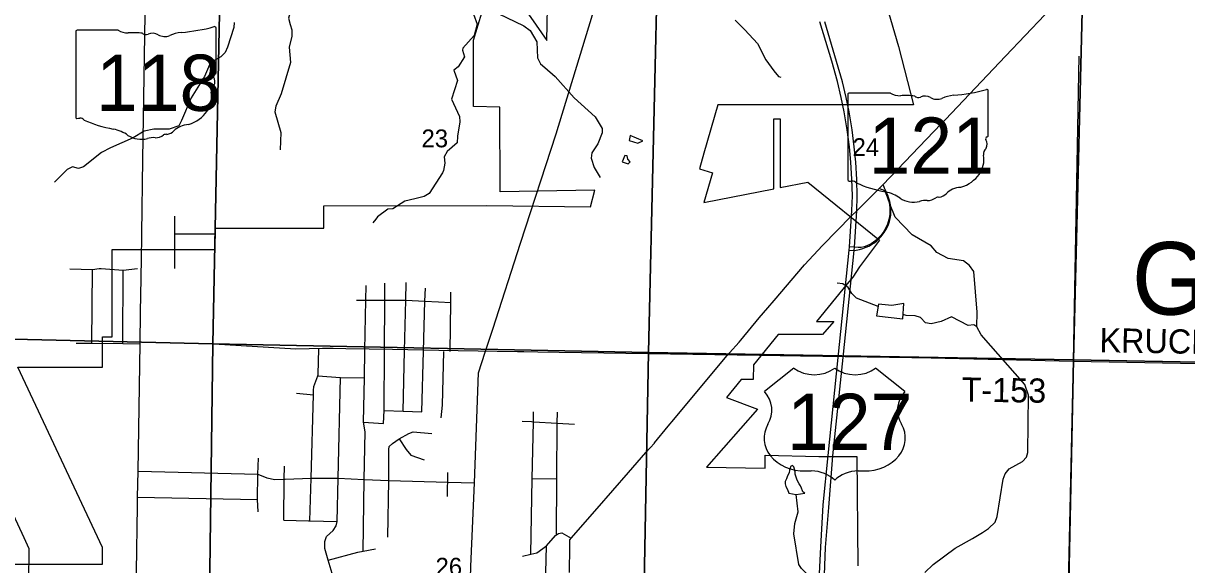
# Model space of a CAD drawing. Extents: x 0 to 68.9, y -26.1 to 22.
# Drawn here: x 4.831 to 7.562, y 18.387 to 19.658 of the extents above; entities that cross this region are included whole.
import ezdxf

# ---------------------------------------------------------------- set-up
doc = ezdxf.new("R2010")
doc.units = 0
for name, color, linetype in [('GM_X_City_Street', 7, 'Continuous'), ('GM_X_Corporation', 7, 'Continuous'), ('GM_X_County_Road', 7, 'Continuous'), ('GM_X_Interchange_Ramps', 7, 'Continuous'), ('GM_X_Minor_Lake', 7, 'Continuous'), ('GM_X_Minor_River', 7, 'Continuous'), ('GM_X_Section_Text', 7, 'Continuous'), ('GM_X_State_Location', 7, 'Continuous'), ('GM_X_State_Route', 7, 'Continuous'), ('GM_X_State_Shield', 7, 'Continuous'), ('GM_X_Township_Road', 7, 'Continuous'), ('GM_X_Township_Road_Text', 7, 'Continuous'), ('GM_X_Township_Text', 7, 'Continuous'), ('GM_X_US_Location', 7, 'Continuous'), ('GM_X_US_Route', 7, 'Continuous'), ('GM_X_US_Shield', 7, 'Continuous')]:
    doc.layers.add(name, color=color, linetype=linetype)

msp = doc.modelspace()

# ---------------------------------------------------------------- linework, layer by layer
at = {"layer": 'GM_X_City_Street'}
for p, q in [((4.9917, 18.9071), (4.9933, 19.0806)), ((5.0641, 18.9065), (5.0649, 19.0787)), ((5.4719, 18.7899), (5.5117, 18.7861)), ((5.1002, 18.6064), (5.3814, 18.6)), ((6.0255, 18.5889), (6.0831, 18.5892)), ((5.0992, 18.546), (5.3803, 18.54))]:
    msp.add_line(p, q, dxfattribs=at)
for points in [[(4.9398, 19.0822), (4.9933, 19.0806), (5.0092, 19.0824), (5.0132, 19.0828), (5.0649, 19.0787), (5.0985, 19.0827)], [(5.6292, 18.722), (5.6313, 18.8257), (5.6327, 18.8912), (5.6351, 19.0083), (5.6358, 19.0426)], [(5.6292, 18.722), (5.6763, 18.7184), (5.6775, 18.749), (5.7223, 18.748), (5.7658, 18.7464), (5.7701, 18.8888), (5.7736, 19.0059), (5.7745, 19.0364)], [(5.6775, 18.749), (5.6783, 18.8904), (5.679, 19.0083), (5.6792, 19.0485)], [(5.7223, 18.748), (5.7258, 18.8896), (5.7287, 19.0082), (5.7297, 19.0496)], [(5.6127, 19.0083), (5.6351, 19.0083), (5.679, 19.0083), (5.7287, 19.0082), (5.7736, 19.0059), (5.8054, 19.0043), (5.8342, 19.0028)], [(5.8328, 18.8878), (5.8342, 19.0028), (5.8345, 19.0271)], [(4.9551, 18.9074), (4.9917, 18.9071), (5.0641, 18.9065), (5.1048, 18.9061)], [(5.5036, 18.4901), (5.5064, 18.5901), (5.5117, 18.7861), (5.512, 18.7963), (5.5127, 18.8058), (5.5221, 18.8309), (5.523, 18.8332), (5.523, 18.8342), (5.5245, 18.893)], [(5.8116, 18.7317), (5.8149, 18.7616), (5.8179, 18.888)], [(5.5221, 18.8309), (5.5755, 18.8267), (5.6313, 18.8257)], [(5.6231, 18.3657), (5.6105, 18.3638), (5.5966, 18.3559), (5.5851, 18.3505), (5.5752, 18.3516), (5.5644, 18.3573), (5.556, 18.3663), (5.5465, 18.398), (5.5384, 18.425), (5.5382, 18.4417), (5.5423, 18.4537), (5.558, 18.4677), (5.5655, 18.4782), (5.5677, 18.4883), (5.5701, 18.59), (5.5755, 18.8267)], [(6.0224, 18.4116), (6.0255, 18.5889), (6.0279, 18.7228), (6.0283, 18.7457)], [(6.0821, 18.4572), (6.0831, 18.5892), (6.0841, 18.7194), (6.0843, 18.7449)], [(5.6283, 18.4188), (5.6312, 18.5874), (5.6331, 18.6991), (5.6292, 18.722)], [(6.0015, 18.7243), (6.0239, 18.723), (6.0279, 18.7228), (6.0841, 18.7194), (6.1248, 18.717)], [(5.6865, 18.4519), (5.6884, 18.5849), (5.6887, 18.6575), (5.6897, 18.6647), (5.6971, 18.6717), (5.713, 18.683), (5.7357, 18.6951), (5.746, 18.699), (5.7898, 18.6954)], [(5.713, 18.683), (5.7291, 18.6576), (5.7402, 18.6444), (5.7719, 18.6331)], [(5.3817, 18.5115), (5.3803, 18.54), (5.3814, 18.6), (5.3826, 18.6369)], [(5.3814, 18.6), (5.4024, 18.591), (5.4209, 18.5874), (5.4432, 18.5881), (5.4456, 18.5882), (5.5064, 18.5901), (5.5093, 18.5901), (5.5701, 18.59), (5.6312, 18.5874), (5.6884, 18.5849), (5.8269, 18.5812), (5.8901, 18.5795)], [(5.4422, 18.4918), (5.4432, 18.5881), (5.4435, 18.6187)], [(5.8263, 18.5475), (5.8267, 18.5698), (5.8269, 18.5812), (5.8272, 18.6033)], [(5.4422, 18.4918), (5.5001, 18.4902), (5.5036, 18.4901), (5.5677, 18.4883)], [(6.0028, 18.4075), (6.0224, 18.4116), (6.0365, 18.4147), (6.059, 18.4313), (6.0802, 18.4559), (6.0821, 18.4572), (6.0871, 18.4606), (6.0948, 18.4616), (6.1165, 18.4491)], [(5.5465, 18.398), (5.6158, 18.4163), (5.6283, 18.4188), (5.6572, 18.4247)], [(6.0526, 18.202), (6.0572, 18.3679), (6.059, 18.4313)]]:
    msp.add_lwpolyline(points, dxfattribs=at)
at = {"layer": 'GM_X_Corporation'}
for points in [[(4.2937, 19.9358), (5.2957, 19.9154), (5.2753, 18.9061), (4.2714, 18.9289)], [(6.3218, 19.8939), (6.2983, 18.8857), (5.2753, 18.9061), (5.2957, 19.9154)], [(6.3218, 19.8939), (7.3211, 19.8752), (7.2954, 18.8682), (6.2983, 18.8857)], [(8.3254, 19.8572), (8.2978, 18.8494), (7.2954, 18.8682), (7.3211, 19.8752)], [(4.2714, 18.9289), (5.2753, 18.9061), (5.2626, 17.9001), (4.25, 17.9235)], [(5.2753, 18.9061), (6.2983, 18.8857), (6.2791, 17.8826), (5.2626, 17.9001)], [(6.2983, 18.8857), (7.2954, 18.8682), (7.2743, 17.8636), (6.2791, 17.8826)], [(7.2954, 18.8682), (8.2978, 18.8494), (8.2824, 17.8496), (7.2743, 17.8636)]]:
    msp.add_lwpolyline(points, close=True, dxfattribs=at)
for points in [[(5.9913, 19.7169), (6.0597, 19.6181), (6.0645, 19.8504)], [(6.8284, 19.7974), (6.885, 19.6036), (6.9201, 19.4673), (6.4613, 19.4672), (6.428, 19.3531), (6.4176, 19.3167), (6.4481, 19.3074), (6.4281, 19.2378), (6.5923, 19.2698), (6.5923, 19.4338), (6.6075, 19.4341), (6.6075, 19.2727), (6.6719, 19.2852), (6.8402, 19.1491), (6.7933, 19.0868), (6.778, 19.0624), (6.7644, 19.0467), (6.6928, 18.9583), (6.7334, 18.9581), (6.707, 18.9279), (6.6028, 18.9279), (6.5449, 18.8563), (6.5437, 18.822), (6.5161, 18.8216), (6.481, 18.7797), (6.5537, 18.7523), (6.4346, 18.616), (6.5723, 18.6136), (6.5723, 18.6228), (6.5723, 18.644), (6.698, 18.6411), (6.7872, 18.6414), (6.7897, 18.3841)], [(4.7703, 18.3886), (5.0167, 18.3887), (5.0167, 18.4272), (4.8182, 18.8508), (5.0165, 18.8509), (5.0165, 18.9225), (5.0392, 18.9225), (5.0392, 19.1269), (5.2809, 19.127), (5.2817, 19.177), (5.5365, 19.1771), (5.5365, 19.2301), (5.9191, 19.2302), (6.1624, 19.2277), (6.172, 19.2662), (5.9497, 19.2623), (5.9496, 19.4617), (5.8873, 19.4628), (5.8873, 19.6186), (5.9181, 19.7194)]]:
    msp.add_lwpolyline(points, dxfattribs=at)
at = {"layer": 'GM_X_County_Road'}
msp.add_line((5.9326, 18.9401), (5.9979, 19.1418), dxfattribs=at)
for points in [[(5.9979, 19.1418), (6.0812, 19.3992), (6.2297, 19.8842)], [(5.876, 18.0868), (5.8738, 18.1354), (5.8764, 18.2174), (5.8815, 18.3829), (5.8901, 18.5795), (5.899, 18.8376), (5.9152, 18.8864), (5.9326, 18.9401)]]:
    msp.add_lwpolyline(points, dxfattribs=at)
at = {"layer": 'GM_X_Interchange_Ramps'}
for points in [[(6.7694, 19.1253), (6.7809, 19.1248), (6.7854, 19.1253), (6.7932, 19.1275), (6.8012, 19.1298), (6.8094, 19.1328), (6.8152, 19.1354), (6.8219, 19.1389), (6.8285, 19.1432), (6.8345, 19.1476), (6.8441, 19.1574), (6.8516, 19.1673), (6.8577, 19.1775), (6.8613, 19.1856), (6.8637, 19.1933), (6.8655, 19.2004), (6.8667, 19.2077), (6.8672, 19.2156), (6.8671, 19.2241), (6.8663, 19.2319), (6.8646, 19.2402), (6.8626, 19.247), (6.86, 19.2545), (6.8561, 19.2629), (6.8541, 19.2667), (6.8519, 19.2716), (6.8505, 19.276), (6.8497, 19.2777), (6.8483, 19.279)], [(6.8406, 19.2715), (6.842, 19.27), (6.8445, 19.2689), (6.8466, 19.2685), (6.8488, 19.2677), (6.8508, 19.2665), (6.8526, 19.2648), (6.8552, 19.2588), (6.8582, 19.2512), (6.8603, 19.2463), (6.8628, 19.2377), (6.864, 19.2316), (6.8647, 19.2252), (6.8648, 19.2184), (6.8645, 19.2113), (6.864, 19.205), (6.8626, 19.1976), (6.8592, 19.1864), (6.8546, 19.1762), (6.8489, 19.167), (6.8434, 19.16), (6.8372, 19.1535), (6.8295, 19.1469), (6.8205, 19.1407), (6.811, 19.1359), (6.8041, 19.1336), (6.797, 19.1317), (6.7903, 19.1319), (6.7817, 19.133), (6.7702, 19.1336)]]:
    msp.add_lwpolyline(points, dxfattribs=at)
at = {"layer": 'GM_X_Minor_Lake'}
for points in [[(6.285, 19.3824), (6.2549, 19.3948), (6.2528, 19.3834)], [(6.2528, 19.3834), (6.2728, 19.3769), (6.285, 19.3824)], [(6.2426, 19.3478), (6.2366, 19.3327), (6.2502, 19.3282)], [(6.2502, 19.3282), (6.2548, 19.3331), (6.2496, 19.3393), (6.2483, 19.3473), (6.2426, 19.3478)], [(6.8691, 18.9959), (6.8379, 18.9987), (6.8332, 18.9714), (6.8955, 18.9648)], [(6.8955, 18.9648), (6.8973, 19.0006), (6.8691, 18.9959)], [(6.6606, 18.558), (6.6595, 18.5602), (6.6574, 18.5666), (6.6552, 18.572), (6.652, 18.5773), (6.6477, 18.5837), (6.6466, 18.588), (6.6423, 18.5998), (6.6423, 18.6051), (6.6391, 18.6169), (6.6359, 18.6201), (6.6316, 18.618), (6.6306, 18.6137), (6.6295, 18.6094), (6.6284, 18.603), (6.6241, 18.5955), (6.622, 18.5891), (6.6188, 18.5826), (6.6188, 18.5773), (6.6209, 18.5709), (6.6242, 18.5634), (6.6274, 18.5548), (6.6451, 18.5522)], [(6.6451, 18.5522), (6.6649, 18.5548), (6.6606, 18.558)]]:
    msp.add_lwpolyline(points, dxfattribs=at)
at = {"layer": 'GM_X_Minor_River'}
for points in [[(5.4326, 19.8304), (5.4309, 19.8179), (5.449, 19.7924), (5.4677, 19.7192), (5.4531, 19.6707), (5.457, 19.6554), (5.4613, 19.6427), (5.4614, 19.6282), (5.4545, 19.602), (5.4576, 19.5665), (5.4361, 19.4926), (5.4238, 19.4635), (5.4212, 19.4502), (5.4355, 19.4023), (5.434, 19.3611)], [(5.8874, 19.6799), (5.8958, 19.656), (5.889, 19.6298), (5.8623, 19.6002), (5.8614, 19.5949), (5.866, 19.5799), (5.8514, 19.5563), (5.8411, 19.5484), (5.85, 19.5241), (5.836, 19.4803), (5.8547, 19.4393), (5.8557, 19.4271), (5.8501, 19.3932), (5.849, 19.3777), (5.8254, 19.357), (5.8188, 19.3448), (5.8204, 19.3296), (5.8174, 19.313), (5.8145, 19.3074), (5.7836, 19.2591), (5.7719, 19.2516), (5.7501, 19.2465), (5.7263, 19.2406), (5.6982, 19.2229), (5.6861, 19.2223), (5.6621, 19.2036), (5.6581, 19.1988), (5.6513, 19.19)], [(5.9457, 19.6814), (6.0053, 19.6527), (6.0203, 19.6417), (6.0361, 19.6151), (6.0373, 19.577), (6.045, 19.5635), (6.0547, 19.5549), (6.0789, 19.5334), (6.1239, 19.4833), (6.1727, 19.4385), (6.1893, 19.4111), (6.1891, 19.4012), (6.1795, 19.3755), (6.1654, 19.354), (6.1637, 19.3415), (6.1705, 19.32), (6.1844, 19.2964)], [(6.5018, 19.6657), (6.5244, 19.6431), (6.5539, 19.6111), (6.5734, 19.5723), (6.5925, 19.5467), (6.6032, 19.5335), (6.6092, 19.5322)], [(5.3256, 19.6602), (5.3246, 19.6488), (5.3104, 19.6025), (5.3049, 19.5901), (5.2941, 19.5796), (5.2703, 19.5663), (5.2557, 19.5338), (5.2244, 19.4834), (5.2022, 19.43), (5.1959, 19.418), (5.173, 19.4096), (5.1373, 19.4096), (5.1145, 19.4054), (5.0884, 19.3895), (5.0357, 19.3662), (5.0146, 19.3547), (4.9723, 19.3216), (4.9601, 19.3173), (4.9465, 19.321), (4.9339, 19.3151), (4.9038, 19.2856)], [(6.975, 19.1201), (6.9617, 19.136), (6.9174, 19.1617), (6.8769, 19.2033), (6.8642, 19.2359)], [(7.0687, 18.946), (7.0698, 18.9802), (7.0616, 19.0753), (7.052, 19.0895), (7.0377, 19.1008), (7.0017, 19.106), (6.975, 19.1201)], [(6.837, 18.9936), (6.7864, 19.0133), (6.7754, 19.0239), (6.7671, 19.0383), (6.7541, 19.0468), (6.7412, 19.0484)], [(7.0687, 18.946), (7.0616, 18.9504), (7.0482, 18.9487), (7.0094, 18.9688), (6.9848, 18.9582), (6.9619, 18.9526), (6.9486, 18.9547), (6.937, 18.9675), (6.9245, 18.9715), (6.9029, 18.9726), (6.896, 18.9743)], [(7.0825, 18.4631), (7.0965, 18.472), (7.1116, 18.4869), (7.1164, 18.5001), (7.1306, 18.5883), (7.1354, 18.6008), (7.1447, 18.612), (7.1759, 18.6293), (7.1852, 18.6397), (7.1885, 18.6507), (7.1898, 18.7851), (7.1815, 18.8099), (7.079, 18.9269), (7.0687, 18.946)], [(6.8267, 18.2973), (6.7933, 18.3009), (6.7696, 18.3177), (6.7571, 18.3191), (6.7444, 18.3155), (6.7212, 18.3155), (6.6577, 18.3782), (6.651, 18.3878), (6.639, 18.4598), (6.6417, 18.4837), (6.6495, 18.5113), (6.6451, 18.5522)], [(6.9465, 18.3685), (6.9666, 18.3879), (7.0178, 18.4261), (7.0586, 18.4483), (7.0825, 18.4631)]]:
    msp.add_lwpolyline(points, dxfattribs=at)
at = {"layer": 'GM_X_State_Route'}
for p, q in [((6.8483, 19.279), (6.9854, 19.4221)), ((6.3446, 18.7121), (6.3577, 18.7278))]:
    msp.add_line(p, q, dxfattribs=at)
for points in [[(6.9854, 19.4221), (6.995, 19.4321), (7.136, 19.581), (7.4128, 19.8732), (7.6543, 20.1282), (8.3388, 20.8623)], [(5.1114, 19.3396), (5.1189, 19.8245), (5.1202, 19.9114)], [(5.1086, 19.1549), (5.1087, 19.1587), (5.1087, 19.1642), (5.1114, 19.3396)], [(6.5782, 18.9902), (6.5929, 19.0077), (6.6644, 19.0911), (6.7067, 19.1364), (6.7749, 19.2059), (6.7871, 19.2183), (6.8406, 19.2715), (6.8483, 19.279)], [(5.1079, 19.1073), (5.1079, 19.1092), (5.1086, 19.1549)], [(5.1048, 18.9061), (5.1059, 18.9804), (5.1071, 19.0597), (5.1079, 19.1073)], [(6.5146, 18.9145), (6.5583, 18.9667), (6.5782, 18.9902)], [(5.099, 18.5289), (5.0992, 18.546), (5.1002, 18.6064), (5.1048, 18.9061)], [(6.4886, 18.8848), (6.5108, 18.9099), (6.5146, 18.9145)], [(6.3577, 18.7278), (6.4821, 18.8774), (6.4886, 18.8848)], [(4.8443, 18.4167), (4.8444, 18.4247), (4.8325, 18.4501), (4.6504, 18.8416)], [(6.3119, 18.6727), (6.3125, 18.6735), (6.3446, 18.7121)], [(6.2514, 18.6035), (6.2923, 18.6503), (6.3119, 18.6727)], [(6.1126, 18.3687), (6.1133, 18.4302), (6.1135, 18.4456), (6.1165, 18.4491), (6.1776, 18.519), (6.2514, 18.6035)], [(5.0947, 18.2516), (5.0948, 18.2546), (5.0948, 18.2589), (5.096, 18.3322), (5.0961, 18.3405), (5.0966, 18.3709), (5.0989, 18.5248), (5.099, 18.5289)], [(4.8436, 18.3575), (4.8442, 18.4127), (4.8443, 18.4167)]]:
    msp.add_lwpolyline(points, dxfattribs=at)
at = {"layer": 'GM_X_State_Shield'}
for p, q in [((4.9537, 19.6388), (4.9537, 19.4386)), ((5.0535, 19.6422), (4.9569, 19.6422)), ((5.2833, 19.5425), (5.2833, 19.6472)), ((5.2832, 19.5425), (5.2833, 19.5425)), ((7.0958, 19.395), (7.0958, 19.4997)), ((6.7662, 19.4913), (6.7662, 19.2912)), ((6.866, 19.4947), (6.7694, 19.4947)), ((7.0957, 19.395), (7.0958, 19.395))]:
    msp.add_line(p, q, dxfattribs=at)
for centre, major_axis, start_param, end_param in [((4.9575, 19.6392), (0.00382, 0), 1.712693, 3.28349), ((5.0764, 19.6654), (0.037, 0), 4.042523, 4.731795), ((5.0887, 19.5299), (0.133, 0), 1.404758, 1.657858), ((5.1189, 19.6402), (0.0107, 0), 3.836095, 5.185415), ((5.1346, 19.6171), (0.0222, 0), 0.950623, 2.079405), ((5.2105, 19.5811), (0.0703, 0), 1.699011, 2.107814), ((5.1659, 19.915), (0.3495, 0), 4.814394, 5.042369), ((5.2796, 19.6476), (0.00367, 0), 6.141152, 7.989035), ((5.1633, 19.6488), (0.0267, 0), 4.081561, 5.145723), ((5.2824, 19.5348), (0.00568, 0), 1.883978, 3.671073), ((5.2463, 19.5216), (0.0341, 0), 5.934695, 6.695948), ((5.2794, 19.5421), (0.00393, 0), 5.05454, 6.418171), ((5.2964, 19.4987), (0.0248, 0), 2.387724, 3.262537), ((6.9784, 19.7675), (0.3495, 0), 4.814394, 5.042369), ((7.0921, 19.5001), (0.00367, 0), 6.141152, 7.989035), ((5.1855, 19.4854), (0.0874, 0), 5.101752, 6.440018), ((6.77, 19.4917), (0.00382, 0), 1.712693, 3.28349), ((6.8889, 19.5179), (0.037, 0), 4.042523, 4.731795), ((6.9012, 19.3824), (0.133, 0), 1.404758, 1.657858), ((6.9314, 19.4927), (0.0107, 0), 3.836095, 5.185415), ((6.9471, 19.4696), (0.0222, 0), 0.950623, 2.079405), ((6.9758, 19.5013), (0.0267, 0), 4.081561, 5.145723), ((7.023, 19.4336), (0.0703, 0), 1.699011, 2.107814), ((4.9575, 19.4382), (0.00385, 0), 3.00124, 4.508301), ((4.9581, 19.4587), (0.0294, 0), 4.665946, 4.897461), ((4.9641, 19.4271), (0.0106, 0), 0.519207, 1.627899), ((5.0979, 19.6069), (0.2524, 0), 4.195997, 4.488961), ((5.2223, 19.3825), (0.0479, 0), 1.647645, 2.488434), ((5.0227, 19.3487), (0.079, 0), 0.823519, 1.323587), ((5.1081, 19.4261), (0.0501, 0), 4.026481, 4.996735), ((5.137, 19.3569), (0.0412, 0), 1.495662, 1.94098), ((5.1407, 19.4111), (0.0267, 0), 4.691044, 5.507374), ((5.1649, 19.3917), (0.00752, 0), 1.147584, 2.315152), ((5.1617, 19.4193), (0.0282, 0), 4.937069, 5.64225), ((7.0949, 19.3873), (0.00568, 0), 1.883978, 3.671073), ((7.0919, 19.3946), (0.00393, 0), 5.05454, 6.418171), ((7.1089, 19.3512), (0.0248, 0), 2.387724, 3.262537), ((7.0588, 19.3741), (0.0341, 0), 5.934695, 6.695948), ((6.998, 19.3379), (0.0874, 0), 5.101752, 6.440018), ((6.77, 19.2907), (0.00385, 0), 3.00124, 4.508301), ((6.7706, 19.3112), (0.0294, 0), 4.665946, 4.897461), ((6.7766, 19.2796), (0.0106, 0), 0.519207, 1.627899), ((6.9104, 19.4594), (0.2524, 0), 4.195997, 4.488961), ((6.8352, 19.2012), (0.079, 0), 0.823519, 1.323587), ((6.9742, 19.2718), (0.0282, 0), 4.937069, 5.64225), ((7.0348, 19.235), (0.0479, 0), 1.647645, 2.488434), ((6.9206, 19.2786), (0.0501, 0), 4.026481, 4.996735), ((6.9495, 19.2094), (0.0412, 0), 1.495662, 1.94098), ((6.9532, 19.2636), (0.0267, 0), 4.691044, 5.507374), ((6.9774, 19.2442), (0.00752, 0), 1.147584, 2.315152)]:
    msp.add_ellipse(centre, major_axis=major_axis, ratio=0.8, start_param=start_param, end_param=end_param, dxfattribs=at)
at = {"layer": 'GM_X_Township_Road'}
for p, q in [((5.1879, 19.1639), (5.2817, 19.1642)), ((5.1862, 19.0828), (5.1865, 19.1335)), ((5.5881, 18.8949), (5.6975, 18.893)), ((6.0382, 18.8872), (6.0882, 18.8864)), ((6.0882, 18.8864), (6.559, 18.8789)), ((6.559, 18.8789), (6.655, 18.8774)), ((6.9283, 18.8735), (7.2956, 18.865))]:
    msp.add_line(p, q, dxfattribs=at)
for points in [[(7.2811, 18.2034), (7.2956, 18.865), (7.309, 19.581)], [(5.1865, 19.1335), (5.1866, 19.1639), (5.1868, 19.2054)], [(5.2778, 18.9061), (5.4702, 18.8942), (5.5331, 18.8958), (5.5581, 18.8954), (5.5881, 18.8949)], [(5.6975, 18.893), (5.8057, 18.8912), (5.8513, 18.8904), (5.8987, 18.8896), (5.9431, 18.8888), (5.9909, 18.888), (6.0057, 18.8878), (6.0382, 18.8872)], [(6.655, 18.8774), (6.9161, 18.8737), (6.9283, 18.8735)], [(7.2956, 18.865), (8.2987, 18.8464), (8.9, 18.842)]]:
    msp.add_lwpolyline(points, dxfattribs=at)
at = {"layer": 'GM_X_US_Route'}
msp.add_line((6.7553, 18.8735), (6.7809, 19.1248), dxfattribs=at)
for points in [[(6.7694, 19.1253), (6.7702, 19.1336), (6.7749, 19.2059), (6.7757, 19.2187), (6.7767, 19.2531), (6.7757, 19.2923), (6.7734, 19.3324), (6.7698, 19.3685), (6.7646, 19.4084), (6.7574, 19.4506), (6.7506, 19.4843), (6.7418, 19.5216), (6.7282, 19.5691), (6.7005, 19.6622)], [(6.7809, 19.1248), (6.7817, 19.133), (6.7871, 19.2183), (6.7881, 19.2528), (6.7871, 19.2919), (6.7848, 19.332), (6.7812, 19.3681), (6.776, 19.408), (6.7689, 19.4503), (6.762, 19.484), (6.7532, 19.5213), (6.7397, 19.5688), (6.7119, 19.6618)], [(6.6651, 17.5474), (6.6654, 17.5534), (6.6933, 18.2057), (6.6968, 18.3043), (6.7024, 18.4282), (6.7084, 18.5276), (6.7196, 18.6432), (6.7431, 18.8737), (6.7694, 19.1253)], [(6.7055, 18.2137), (6.714, 18.4276), (6.7211, 18.5216), (6.7311, 18.6427), (6.7553, 18.8735)]]:
    msp.add_lwpolyline(points, dxfattribs=at)
at = {"layer": 'GM_X_US_Shield'}
for p, q in [((6.6391, 18.8489), (6.5705, 18.794)), ((6.9, 18.794), (6.8314, 18.8489)), ((6.6666, 18.6072), (6.6803, 18.6072)), ((6.7902, 18.6072), (6.8039, 18.6072))]:
    msp.add_line(p, q, dxfattribs=at)
for centre, major_axis, start_param, end_param in [((6.6872, 18.8882), (-0.0687, 0), 0.795399, 2.346194), ((6.7833, 18.8882), (-0.0687, 0), 0.795399, 2.346194), ((6.4917, 18.7499), (0.0961, 0), 5.838949, 6.894067), ((6.9788, 18.7499), (-0.0961, 0), 5.672304, 6.727422), ((6.6655, 18.6841), (0.0961, 0), 2.702327, 4.723529), ((6.805, 18.6841), (-0.0961, 0), 1.559657, 3.580859), ((6.6803, 18.5523), (-0.0687, 0), 3.785094, 4.712389), ((6.7902, 18.5523), (-0.0687, 0), 4.712389, 5.639684)]:
    msp.add_ellipse(centre, major_axis=major_axis, ratio=0.8, start_param=start_param, end_param=end_param, dxfattribs=at)

# ---------------------------------------------------------------- texts
at = {"layer": 'GM_X_Section_Text'}
for s, p in [('23', (5.7655, 19.3672)), ('24', (6.7772, 19.3467)), ('26', (5.7984, 18.3614))]:
    msp.add_text(s, height=0.04186, rotation=0, dxfattribs=at).set_placement(p)
at = {"layer": 'GM_X_State_Location'}
for s, p in [('s', (5.1148, 19.5254)), ('r', (5.1148, 19.5254)), ('s', (6.9273, 19.3779)), ('r', (6.9273, 19.3779))]:
    msp.add_text(s, height=0.000189, dxfattribs=at).set_placement(p)
for s, p in [('118', (5.0479, 19.5116)), ('121', (6.8604, 19.3641))]:
    msp.add_text(s, height=0.000189, rotation=0, dxfattribs=at).set_placement(p)
at = {"layer": 'GM_X_State_Shield'}
for s, p in [('118', (5.0013, 19.4528)), ('121', (6.8148, 19.3053))]:
    msp.add_text(s, height=0.13184, dxfattribs=at).set_placement(p)
at = {"layer": 'GM_X_Township_Road_Text'}
for s, rotation, p in [('KRUCKEBERG', 358.9862, (7.3563, 18.8862)), ('T-153', 359.1569, (7.0328, 18.7702))]:
    msp.add_text(s, height=0.05682, rotation=rotation, dxfattribs=at).set_placement(p)
at = {"layer": 'GM_X_Township_Text'}
msp.add_text('GREENVILLE', height=0.17045, rotation=0, dxfattribs=at).set_placement((7.4327, 18.9742))
at = {"layer": 'GM_X_US_Location'}
for s, p in [('0', (6.7353, 18.7225)), ('/', (6.7354, 18.7225))]:
    msp.add_text(s, height=0.000189, dxfattribs=at).set_placement(p)
msp.add_text('127', height=0.000189, rotation=0, dxfattribs=at).set_placement((6.6771, 18.6833))
at = {"layer": 'GM_X_US_Shield'}
msp.add_text('127', height=0.13184, dxfattribs=at).set_placement((6.6234, 18.6567))

doc.saveas('drawing.dxf')
